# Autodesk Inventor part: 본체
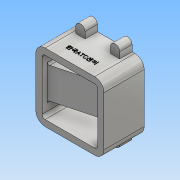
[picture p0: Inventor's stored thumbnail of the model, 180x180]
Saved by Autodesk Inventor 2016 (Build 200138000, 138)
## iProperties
Created: 2018-01
Part Number: 본체
Material: 알루미늄 6061
Document SubType Name: Modeling
Designer: Administrator
Mass: 994.428 g
Surface Area: 845.509 cm^2
Volume: 368.307 cm^3
Density: 2.7 g/cm^3
Appearance: 알루미늄 - 평지
Author: Administrator
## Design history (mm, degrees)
sketch "스케치2"
  geometry: L1 (40, -55)-(-40, -55); L2 (-55, -40)-(-55, 40); L3 (-40, 55)-(40, 55); L4 (55, 40)-(55, -40); L5 (0, 55)-(0, -55); L6 (55, 0)-(-55, 0); A1 r 15 centre (40, -40) between (40, -55) and (55, -40); A2 r 15 centre (-40, -40) between (-55, -40) and (-40, -55); A3 r 15 centre (-40, 40) between (-40, 55) and (-55, 40); A4 r 15 centre (40, 40) between (55, 40) and (40, 55); 5 further points
  constraints: 12 end point, 8 point on circle, 8 tangent, 6 point on line, 5 midpoint, 4 centre point, 3 equal radius, 2 parallel, 1 coincident, 1 horizontal, 1 perpendicular
  dimensions: "d0" = 110 distance of point (-55, 55) point (55, 55); "d1" = 110 distance of point (-55, -55) point (-55, 55); "d2" = 15 radius of A1
extrude "돌출1" new body sketch "스케치2" distance "d3" = 65; taper "d4" = 0 deg
sketch "스케치3"
  geometry: L1 (40, 55)-(-40, 55) reference; L2 (-55, 40)-(-55, -40) reference; L3 (-35.5, 65)-(-35.5, 50.607); L4 (-35.5, 50.607)-(-20.5, 50.607); L5 (-20.5, 50.607)-(-20.5, 65); L6 (20.5, 65)-(20.5, 49.182); L7 (20.5, 49.182)-(35.5, 49.182); L8 (35.5, 49.182)-(35.5, 65); A1 r 7.5 centre (-28, 65) between (-20.5, 65) and (-35.5, 65); A2 r 7.5 centre (28, 65) between (35.5, 65) and (20.5, 65); 1 further point
  constraints: 12 end point, 4 point on circle, 2 centre point, 2 perpendicular, 2 tangent, 2 vertical
  dimensions: "d5" = 15 diameter of A1; "d6" = 15 diameter of A2; "d7" = 56 distance of A1.centre A2.centre; "d8" = 27 distance from line of A1.centre L2; "d9" = 10 distance from line of A1.centre L1; "d11" = 10 distance from line of L1 A2.centre; "d12" = 15 distance of L3.end L4.end; "d13" = 15 distance of L6.end L7.end; "d14" = 14.3934 distance of L4.end L5.end; "d15" = 14.3934 distance of L3.start L3.end; "d16" = 80 distance of L1.start L1.end (derived); "d17" = 15.81759 distance of L6.start L6.end; "d18" = 15.81759 distance of L7.end L8.end
extrude "돌출2" join sketch "스케치3" distance "d19" = 20; taper "d20" = 0 deg
sketch "스케치4"
  geometry: A1 r 7.5 centre (-28, 65) between (-20.5, 65) and (-35.5, 65) reference; 2 further points
  constraints: 1 coincident
hole "구멍1" sketch "스케치4" at (-28, 65) diameter "d21" = 3.242; stored, may be unused: countersink angle "d25" = 90 deg, drill point angle "d27" = 118 deg; dims "d22" = 8, "d23" = 4, "d24" = 2, "d26" = 11
node "작업 평면1"
sketch "스케치5"
  geometry: L1 (-15, 0)-(-15, 65) reference; L2 (95, 0)-(80, 0) reference; 2 further points
  constraints: 1 other
  dimensions: "d35" = 55 distance from line of L1 point (40, 20); "d36" = 20 distance from line of L2 point (40, 20)
feature "엠보싱1" sketch "스케치5" dims "d5" = 15, "d37" = 0.5, "d38" = 0
sketch "스케치6"
  geometry: L1 (55, -40)-(55, 40) reference; L2 (20.5, 55)-(-20.5, 55) reference; L3 (-55, 40)-(-55, -40) reference; L4 (-20.5, -55)-(20.5, -55) reference; L5 (-45, 45)-(45, 45); L6 (45, 54.142)-(45, -45); L7 (45, -45)-(-45, -45); L8 (-45, -45)-(-45, -25); L9 (-45, -25)-(35, -25); L10 (35, -25)-(35, 25); L11 (35, 25)-(-45, 25); L12 (-45, 25)-(-45, 45); A1 r 15 centre (40, -40) between (40, -55) and (55, -40) reference; A2 r 15 centre (40, 40) between (55, 40) and (40, 55) reference; A3 r 15 centre (-40, 40) between (-40, 55) and (-55, 40) reference; A4 r 15 centre (-40, -40) between (-55, -40) and (-40, -55) reference; 8 further points
  constraints: 16 end point, 6 perpendicular, 5 point on line, 4 point on circle, 1 horizontal, 1 parallel
  dimensions: "d39" = 10 distance between parallel lines of L7 L4; "d40" = 10 distance between parallel lines of L2 L5; "d41" = 30 distance between parallel lines of L11 L2; "d42" = 10 distance between parallel lines of L1 L6; "d43" = 20 distance between parallel lines of L1 L10; "d44" = 30 distance between parallel lines of L4 L9; "d45" = 10 distance from line of L3.end L8; "d46" = 10 distance between parallel lines of L3 L12
extrude "돌출3" cut sketch "스케치6" stored distance "d55" = 20; taper "d56" = 0 deg
sketch "스케치7"
  geometry: L1 (77, -65)-(-3, -65) reference; L2 (-3, -56.436)-(77, -35); L3 (97, -65)-(97, 0) reference; L4 (-13, -65)-(-13, 0) reference; L5 (-3, -56.436)-(-3, -72.207); L6 (77, -35)-(77, -72.207); L7 (77, -72.207)-(-3, -72.207); 3 further points
  constraints: 8 end point, 2 vertical, 1 perpendicular
  dimensions: "d59" = 30 distance from line of L1 L2.end; "d61" = 10 distance between parallel lines of L4 L5; "d62" = 105 deg angle of L2 L5; "d63" = 20 distance from line of L3 L6.end; "d65" = 37.20743 distance of L2.end L6.end
extrude "돌출4" cut sketch "스케치7" distance "d66" = 50; taper "d67" = 0 deg
sketch "스케치9"
  geometry: L1 (-40, 65)-(-55, 65) reference; L2 (-55, 65)-(30, 65); L3 (-40, 65)-(45, 65) reference; L4 (30, 65)-(30, 50); L5 (30, 50)-(25, 50); L6 (25, 50)-(25, 45); L7 (25, 45)-(-22, 45); L8 (-22, 45)-(-22, 49); L9 (-22, 49)-(-36, 49); L10 (-55, 0)-(-55, 65) reference; L11 (-36, 49)-(-36, 57.5); L12 (-36, 57.5)-(-55, 57.5); L13 (-55, 65)-(-55, 57.5); 2 further points
  constraints: 20 end point, 6 perpendicular, 2 point on line, 2 vertical, 1 collinear
  dimensions: "d78" = 7.5 distance between parallel lines of L1 L12; "d79" = 16 distance from line of L2 L9.end; "d80" = 20 distance from line of L2 L7.end; "d81" = 15 distance of L2.end L4.end; "d82" = 5 distance of L4.end L5.end; "d83" = 47 distance of L6.end L7.end; "d84" = 19 distance of L11.end L12.end; "d85" = 14 distance of L8.end L9.end
revolve "회전1" sketch "스케치9" stored, may be unused: angle "d86" = 90 deg
chamfer "모따기1" distance "d87" = 1; stored, may be unused: second distance "d88" = 2, angle "d89" = 45 deg
sketch "스케치10"
  geometry: L1 (-55, 0)-(-55, 65) reference; L2 (35, 30)-(-45, 8.564) reference; L3 (20, 31.157)-(-55, 11.061); L4 (-55, 11.061)-(-55, 29.061); L5 (-55, 29.061)-(-17, 39.243); L6 (-17, 39.243)-(-17, 54.361); L7 (-17, 54.361)-(20, 54.361); L8 (20, 54.361)-(20, 31.157); L9 (-22, 49)-(-22, 65) reference; 3 further points
  constraints: 12 end point, 2 parallel, 2 perpendicular, 2 point on line
  dimensions: "d90" = 5 distance between parallel lines of L2 L3; "d91" = 37 distance of L6.end L7.end; "d92" = 75 deg angle of L1 L5; "d93" = 18 distance of L3.end L4.end; "d94" = 5 distance between parallel lines of L9 L6; "d95" = 23.20373 distance of L7.end L3.start
extrude "돌출5" cut sketch "스케치10" stored distance "d96" = 30; taper "d97" = 0 deg
fillet "모깎기1" dims "d98" = 5
fillet "모깎기2" dims "d99" = 3
node "솔리드1"
mirror "대칭1"
pattern_linear "직사각형 패턴1" dims "d30" = 56
other parameters: "d34" = 39
